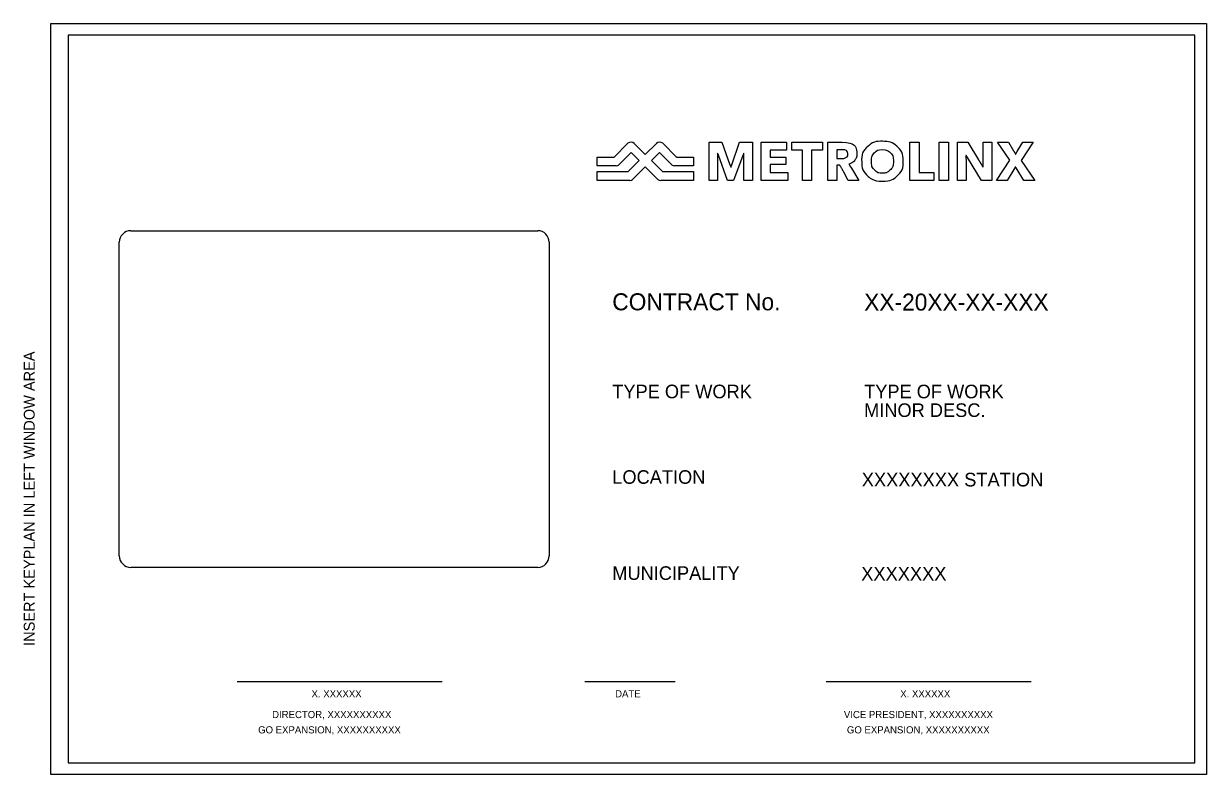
# Model space of a CAD drawing. Extents: x 316474.847 to 316475.672, y 846474.851 to 846475.375.
import ezdxf

# ---------------------------------------------------------------- set-up
doc = ezdxf.new("R2010")
doc.units = 0
for name, color, linetype in [('c_Legend', 7, 'Continuous'), ('c_NO_Print', 7, 'Continuous'), ('CPG_Border', 7, 'Continuous'), ('CPG_Border_Text', 7, 'Continuous'), ('Default', 7, 'Continuous')]:
    doc.layers.add(name, color=color, linetype=linetype)

msp = doc.modelspace()

# ---------------------------------------------------------------- linework, layer by layer
at = {"layer": 'c_Legend'}
for p, q in [((316475.26011, 846475.27564), (316475.24673, 846475.27564)), ((316474.99567, 846474.91565), (316475.13867, 846474.91565)), ((316475.23806, 846474.91565), (316475.30111, 846474.91565)), ((316475.40652, 846474.91565), (316475.54952, 846474.91565))]:
    msp.add_line(p, q, dxfattribs=at)
for points in [[(316475.24673, 846475.27564), (316475.24673, 846475.28179), (316475.2586, 846475.28179), (316475.26822, 846475.29139)], [(316475.27262, 846475.29135), (316475.28038, 846475.28367), (316475.28814, 846475.29135)], [(316475.29253, 846475.29139), (316475.30216, 846475.28179), (316475.31403, 846475.28179), (316475.31403, 846475.27564), (316475.30065, 846475.27564)], [(316475.33083, 846475.27996), (316475.33083, 846475.26553), (316475.32487, 846475.26553), (316475.32487, 846475.29207), (316475.33384, 846475.29207), (316475.33942, 846475.27639)], [(316475.3407, 846475.27636), (316475.34603, 846475.29207), (316475.35524, 846475.29207), (316475.35524, 846475.26553)], [(316475.37971, 846475.26553), (316475.36113, 846475.26553), (316475.36113, 846475.29207), (316475.379, 846475.29207), (316475.379, 846475.28666), (316475.3674, 846475.28666), (316475.3674, 846475.28163), (316475.37838, 846475.28163), (316475.37838, 846475.27654), (316475.3674, 846475.27654), (316475.3674, 846475.27096), (316475.37971, 846475.27096), (316475.37971, 846475.26553)], [(316475.40391, 846475.28666), (316475.39641, 846475.28666), (316475.39641, 846475.26553), (316475.39005, 846475.26553), (316475.39005, 846475.28666), (316475.38252, 846475.28666), (316475.38252, 846475.29207), (316475.40391, 846475.29207), (316475.40391, 846475.28666)], [(316475.41608, 846475.2761), (316475.41392, 846475.2761), (316475.41392, 846475.26553), (316475.40768, 846475.26553), (316475.40768, 846475.29207), (316475.41771, 846475.29207)], [(316475.41392, 846475.28693), (316475.41392, 846475.28068), (316475.41813, 846475.28068)], [(316475.418, 846475.28693), (316475.41392, 846475.28693)], [(316475.48173, 846475.26553), (316475.46507, 846475.26553), (316475.46507, 846475.29207), (316475.47142, 846475.29207), (316475.47142, 846475.27096), (316475.48173, 846475.27096), (316475.48173, 846475.26553)], [(316475.492, 846475.26553), (316475.48553, 846475.26553), (316475.48553, 846475.29207), (316475.492, 846475.29207), (316475.492, 846475.26553)], [(316475.50421, 846475.2761), (316475.50423, 846475.26553), (316475.49813, 846475.26553), (316475.49813, 846475.29207), (316475.50533, 846475.29207), (316475.51286, 846475.27989)], [(316475.51617, 846475.2761), (316475.51604, 846475.29207), (316475.52226, 846475.29207), (316475.52226, 846475.26553)], [(316475.53815, 846475.27417), (316475.53297, 846475.26553), (316475.52539, 846475.26553), (316475.53467, 846475.27953), (316475.52614, 846475.29207), (316475.53375, 846475.29207), (316475.53737, 846475.28611)], [(316475.5402, 846475.28618), (316475.5437, 846475.29207), (316475.5511, 846475.29207), (316475.54272, 846475.27948), (316475.55226, 846475.26553)], [(316475.26964, 846475.2655), (316475.24673, 846475.2655), (316475.24673, 846475.27165), (316475.26836, 846475.27165), (316475.27604, 846475.2793), (316475.27041, 846475.28488), (316475.26173, 846475.27623)], [(316475.29903, 846475.27623), (316475.29035, 846475.28488), (316475.28472, 846475.2793), (316475.2924, 846475.27165), (316475.31403, 846475.27165), (316475.31403, 846475.2655), (316475.29112, 846475.2655)], [(316475.33135, 846475.28309), (316475.33083, 846475.28449)], [(316475.34848, 846475.28299), (316475.34201, 846475.26553), (316475.33783, 846475.26553), (316475.33135, 846475.28309)], [(316475.35524, 846475.26553), (316475.34904, 846475.26553), (316475.34902, 846475.28129)], [(316475.34904, 846475.28449), (316475.34904, 846475.28449)], [(316475.42316, 846475.27716), (316475.42249, 846475.27691)], [(316475.50412, 846475.28295), (316475.50412, 846475.28295)], [(316475.52226, 846475.26553), (316475.51497, 846475.26553), (316475.50519, 846475.28149)], [(316475.53868, 846475.28389), (316475.53883, 846475.28389)], [(316475.28922, 846475.26614), (316475.28038, 846475.27495), (316475.27154, 846475.26614)], [(316475.34014, 846475.27471), (316475.34014, 846475.27471)], [(316475.42933, 846475.26553), (316475.42187, 846475.26553), (316475.41887, 846475.27117)], [(316475.42415, 846475.27405), (316475.42933, 846475.26553)], [(316475.51604, 846475.2747), (316475.51618, 846475.27471)], [(316475.53869, 846475.27485), (316475.53854, 846475.27486)], [(316475.55226, 846475.26553), (316475.5444, 846475.26553), (316475.53907, 846475.27418)]]:
    msp.add_lwpolyline(points, dxfattribs=at)
for centre, radius, start, end in [((316475.2704, 846475.28852), 0.0036, 51.84972, 127.27899), ((316475.29036, 846475.28852), 0.0036, 52.72101, 128.15028), ((316475.25922, 846475.28059), 0.00503, 280.17536, 299.87114), ((316475.30154, 846475.28059), 0.00503, 240.12886, 259.82464), ((316475.26936, 846475.26947), 0.00398, 273.96872, 303.17718), ((316475.29139, 846475.26947), 0.00398, 236.82282, 266.03128)]:
    msp.add_arc(centre, radius, start, end, dxfattribs=at)
for points, degree in [([(316475.41771, 846475.29207), (316475.42685, 846475.2921), (316475.42797, 846475.28541), (316475.42813, 846475.28308), (316475.42761, 846475.28163), (316475.4272, 846475.28047), (316475.42662, 846475.27964), (316475.42561, 846475.27819), (316475.42443, 846475.27775), (316475.42384, 846475.27732), (316475.42316, 846475.27716)], 3), ([(316475.41813, 846475.28068), (316475.41921, 846475.28079), (316475.42037, 846475.28135), (316475.42197, 846475.28239), (316475.42165, 846475.28472), (316475.42078, 846475.28693), (316475.418, 846475.28693)], 3), ([(316475.44559, 846475.26485), (316475.43959, 846475.26493), (316475.43554, 846475.26856), (316475.43159, 846475.27258), (316475.43133, 846475.27842), (316475.43125, 846475.28515), (316475.43566, 846475.28924), (316475.43989, 846475.29283), (316475.44599, 846475.29278), (316475.4517, 846475.29266), (316475.45573, 846475.28946), (316475.46009, 846475.28564), (316475.46035, 846475.27921), (316475.4603, 846475.2725), (316475.45594, 846475.26841), (316475.45174, 846475.26471), (316475.44559, 846475.26485)], 3), ([(316475.44574, 846475.28706), (316475.44261, 846475.28705), (316475.44075, 846475.28521), (316475.43825, 846475.28305), (316475.43823, 846475.27895), (316475.43813, 846475.27493), (316475.44052, 846475.2727), (316475.44248, 846475.27049), (316475.44577, 846475.27067), (316475.44876, 846475.27047), (316475.45094, 846475.2725), (316475.45346, 846475.27481), (316475.45353, 846475.27879), (316475.45343, 846475.28302), (316475.45081, 846475.28527), (316475.44893, 846475.28699), (316475.44574, 846475.28706)], 3), ([(316475.53737, 846475.28611), (316475.53817, 846475.28479), (316475.53868, 846475.28389)], 2), ([(316475.53883, 846475.28389), (316475.53946, 846475.28485), (316475.5402, 846475.28618)], 2), ([(316475.33083, 846475.28449), (316475.33083, 846475.2829), (316475.33083, 846475.27996)], 2), ([(316475.33135, 846475.28309), (316475.33083, 846475.28392), (316475.33135, 846475.28309)], 2), ([(316475.34904, 846475.28449), (316475.34874, 846475.28369), (316475.34848, 846475.28299)], 2), ([(316475.34902, 846475.28129), (316475.34902, 846475.28385), (316475.34904, 846475.28449)], 2), ([(316475.50519, 846475.28149), (316475.50452, 846475.2826), (316475.50412, 846475.28295)], 2), ([(316475.50412, 846475.28295), (316475.50412, 846475.28217), (316475.50421, 846475.2761)], 2), ([(316475.51286, 846475.27989), (316475.51438, 846475.27747), (316475.51604, 846475.2747)], 2), ([(316475.33942, 846475.27639), (316475.3398, 846475.27542), (316475.34014, 846475.27471)], 2), ([(316475.34014, 846475.27471), (316475.34014, 846475.27471), (316475.3407, 846475.27636)], 2), ([(316475.41887, 846475.27117), (316475.41807, 846475.27268), (316475.41772, 846475.27334), (316475.41725, 846475.2742), (316475.41701, 846475.27463), (316475.41671, 846475.27525), (316475.41608, 846475.2761), (316475.41632, 846475.27598), (316475.41608, 846475.2761)], 3), ([(316475.42249, 846475.27691), (316475.42249, 846475.27691), (316475.42267, 846475.2765), (316475.42276, 846475.27632), (316475.423, 846475.2759), (316475.42329, 846475.27545), (316475.42355, 846475.27498), (316475.42367, 846475.27478), (316475.42415, 846475.27405)], 3), ([(316475.51618, 846475.27471), (316475.51618, 846475.27541), (316475.51617, 846475.2761)], 2), ([(316475.53854, 846475.27486), (316475.5383, 846475.27447), (316475.53815, 846475.27417)], 2), ([(316475.53907, 846475.27418), (316475.53882, 846475.27454), (316475.53869, 846475.27485)], 2)]:
    msp.add_open_spline(points, degree=degree, dxfattribs=at)
at = {"layer": 'c_NO_Print'}
msp.add_lwpolyline([(316474.86557, 846475.37491), (316475.67187, 846475.37491), (316475.67187, 846474.85091), (316474.86557, 846474.85091)], close=True, dxfattribs=at)
at = {"layer": 'CPG_Border'}
msp.add_lwpolyline([(316475.66387, 846474.8589), (316475.66387, 846475.36689), (316474.87757, 846475.36689), (316474.87757, 846474.8589)], close=True, dxfattribs=at)
at = {"layer": 'Default'}
for points in [[(316474.92132, 846475.2304), (316475.20532, 846475.2304)], [(316474.91332, 846475.0034), (316474.91332, 846475.2224)], [(316475.21332, 846475.2224), (316475.21332, 846475.0034)], [(316475.20532, 846474.9954), (316474.92132, 846474.9954)]]:
    msp.add_lwpolyline(points, dxfattribs=at)
for centre, start, end in [((316474.92132, 846475.2224), 90, 180), ((316475.20532, 846475.2224), 360, 90), ((316474.92132, 846475.0034), 180, 270), ((316475.20532, 846475.0034), 270, 0)]:
    msp.add_arc(centre, 0.008, start, end, dxfattribs=at)

# ---------------------------------------------------------------- texts
at = {"layer": 'c_NO_Print'}
msp.add_text('INSERT KEYPLAN IN LEFT WINDOW AREA', height=0.0076, rotation=90, dxfattribs=at).set_placement((316474.85428, 846474.94056))
at = {"layer": 'CPG_Border_Text'}
for s, height, p in [('CONTRACT No.', 0.011875, (316475.25732, 846475.17482)), ('XX-20XX-XX-XXX', 0.0118618, (316475.4331, 846475.17461)), ('TYPE OF WORK', 0.0095, (316475.25732, 846475.11342)), ('TYPE OF WORK', 0.0095, (316475.43306, 846475.11339)), ('MINOR DESC.', 0.0095, (316475.43306, 846475.10037)), ('LOCATION', 0.0095, (316475.25732, 846475.05371)), ('XXXXXXXX STATION', 0.009525, (316475.43141, 846475.05186)), ('MUNICIPALITY', 0.0095, (316475.25732, 846474.98664)), ('XXXXXXX', 0.009525, (316475.43104, 846474.98622)), ('X. XXXXXX', 0.005, (316475.04746, 846474.90465)), ('DATE', 0.005, (316475.25929, 846474.90465)), ('X. XXXXXX', 0.005, (316475.45827, 846474.90465)), ('DIRECTOR, XXXXXXXXXX', 0.005, (316475.01993, 846474.89016)), ('VICE PRESIDENT, XXXXXXXXXX', 0.005, (316475.41894, 846474.89016)), ('GO EXPANSION, XXXXXXXXXX', 0.005, (316475.01018, 846474.87949)), ('GO EXPANSION, XXXXXXXXXX', 0.005, (316475.42105, 846474.87949))]:
    msp.add_text(s, height=height, dxfattribs=at).set_placement(p)

doc.saveas('drawing.dxf')
